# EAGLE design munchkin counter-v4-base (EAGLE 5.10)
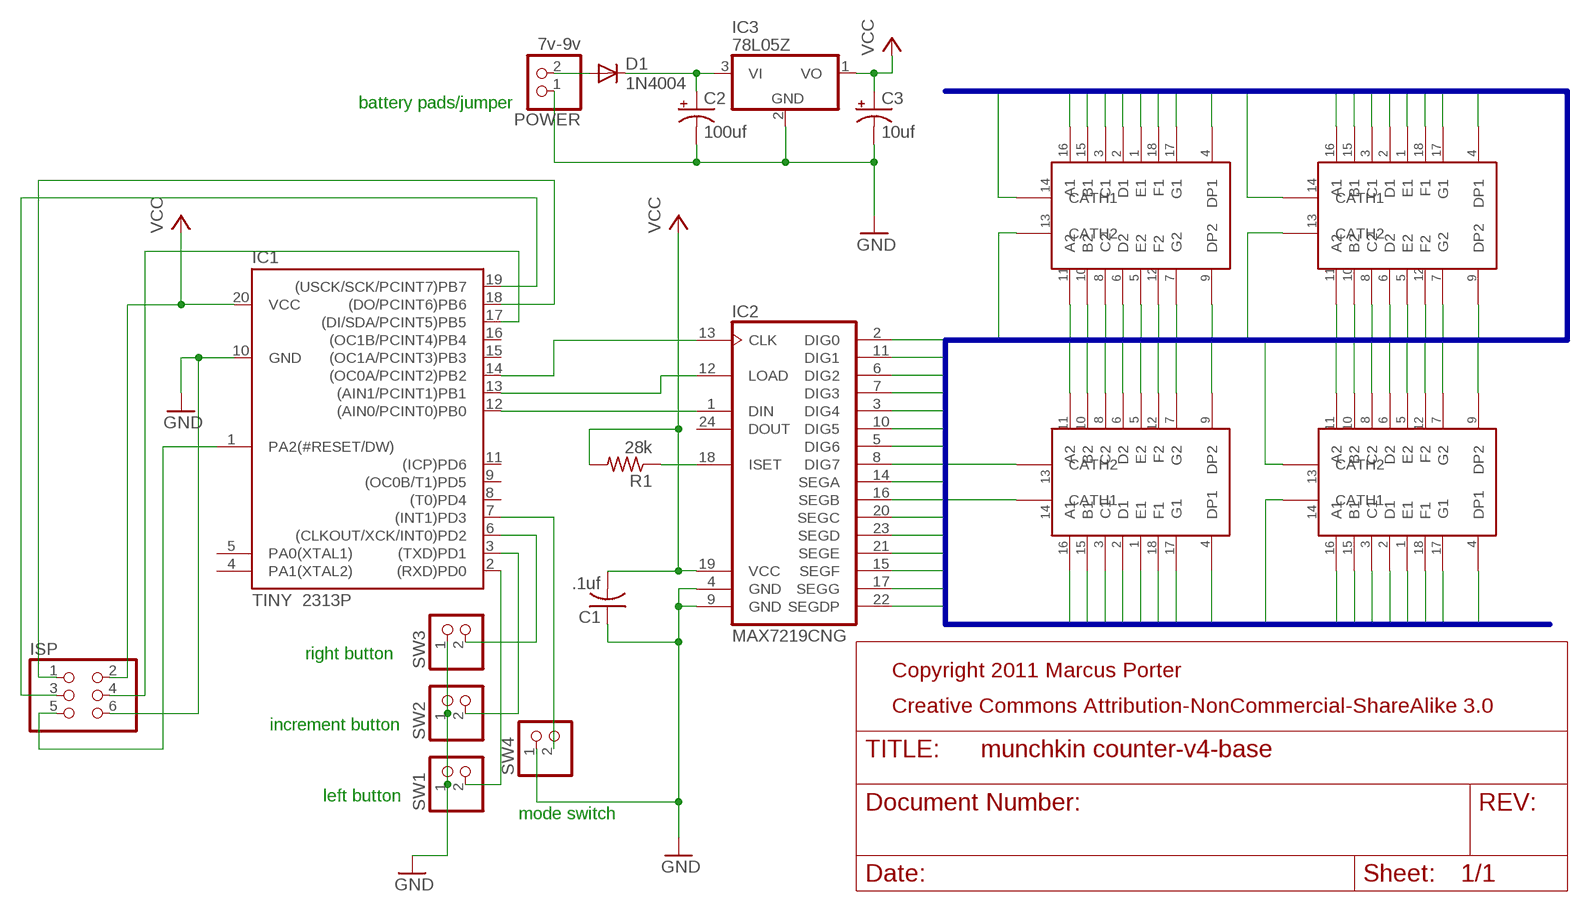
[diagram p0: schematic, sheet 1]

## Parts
C1  .1uf  C-US025-025X050  [C025-025X050]
C2  100uf  CPOL-USE2.5-5  [E2,5-5]
C3  10uf  CPOL-USE2.5-5  [E2,5-5]
D1  1N4004  [DO41-10]
DISPLAY1  DUAL7SEGMENTLEDDUAL7SEGMENT-VIA-CABLE  [2X9HEADER]
DISPLAY2  DUAL7SEGMENTLEDDUAL7SEGMENT-VIA-CABLE  [2X9HEADER]
DISPLAY3  DUAL7SEGMENTLEDDUAL7SEGMENT-VIA-CABLE  [2X9HEADER]
DISPLAY4  DUAL7SEGMENTLEDDUAL7SEGMENT-VIA-CABLE  [2X9HEADER]
IC1  TINY 2313P  TINY2313P  [DIL20]
IC2  MAX7219CNG  [DIL24-3]
IC3  78L05Z  [TO92]
ISP  PINHD-2X3  [2X03]
POWER  7v-9v  PINHD-1X2  [1X02]
R1  28k  R-US_0204/7  [0204/7]
SW1  PINHD-1X2  [1X02]
SW2  PINHD-1X2  [1X02]
SW3  PINHD-1X2  [1X02]
SW4  PINHD-1X2  [1X02]

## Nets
DIG0: DISPLAY1.P14/CATH1(CATH1) IC2.2(DIG0)
DIG1: DISPLAY1.P13/CATH2(CATH2) IC2.11(DIG1)
DIG2: DISPLAY2.P14/CATH1(CATH1) IC2.6(DIG2)
DIG3: DISPLAY2.P13/CATH2(CATH2) IC2.7(DIG3)
DIG4: DISPLAY3.P14/CATH1(CATH1) IC2.3(DIG4)
DIG5: DISPLAY3.P13/CATH2(CATH2) IC2.10(DIG5)
DIG6: DISPLAY4.P14/CATH1(CATH1) IC2.5(DIG6)
DIG7: DISPLAY4.P13/CATH2(CATH2) IC2.8(DIG7)
GND: C1.1 C2.- C3.- IC1.10(GND) IC2.4(GND) IC2.9(GND) IC3.2(GND) ISP.6 POWER.1 SW1.1 SW2.1 SW3.1 SW4.1
N$1: IC1.7((INT1)PD3) SW4.2
N$2: IC1.12((AIN0/PCINT0)PB0) IC2.1(DIN)
N$3: IC1.13((AIN1/PCINT1)PB1) IC2.12(LOAD)
N$4: IC1.14((OC0A/PCINT2)PB2) IC2.13(CLK)
N$5: IC1.2((RXD)PD0) SW1.2
N$6: IC1.3((TXD)PD1) SW2.2
N$7: IC1.6((CLKOUT/XCK/INT0)PD2) SW3.2
N$8: IC2.18(ISET) R1.1
N$9: IC1.18((DO/PCINT6)PB6) ISP.1
N$10: D1.A POWER.2
N$11: IC1.19((USCK/SCK/PCINT7)PB7) ISP.3
N$12: IC1.17((DI/SDA/PCINT5)PB5) ISP.4
N$13: IC1.1(PA2(#RESET/DW)) ISP.5
N$14: C2.+ D1.C IC3.3(VI)
SEGA: DISPLAY1.P11/A2(A2) DISPLAY1.P16/A1(A1) DISPLAY2.P11/A2(A2) DISPLAY2.P16/A1(A1) DISPLAY3.P11/A2(A2) DISPLAY3.P16/A1(A1) DISPLAY4.P11/A2(A2) DISPLAY4.P16/A1(A1) IC2.14(SEGA)
SEGB: DISPLAY1.P10/B2(B2) DISPLAY1.P15/B1(B1) DISPLAY2.P10/B2(B2) DISPLAY2.P15/B1(B1) DISPLAY3.P10/B2(B2) DISPLAY3.P15/B1(B1) DISPLAY4.P10/B2(B2) DISPLAY4.P15/B1(B1) IC2.16(SEGB)
SEGC: DISPLAY1.P3/C1(C1) DISPLAY1.P8/C2(C2) DISPLAY2.P3/C1(C1) DISPLAY2.P8/C2(C2) DISPLAY3.P3/C1(C1) DISPLAY3.P8/C2(C2) DISPLAY4.P3/C1(C1) DISPLAY4.P8/C2(C2) IC2.20(SEGC)
SEGD: DISPLAY1.P2/D2(D1) DISPLAY1.P6/D2(D2) DISPLAY2.P2/D2(D1) DISPLAY2.P6/D2(D2) DISPLAY3.P2/D2(D1) DISPLAY3.P6/D2(D2) DISPLAY4.P2/D2(D1) DISPLAY4.P6/D2(D2) IC2.23(SEGD)
SEGDP: DISPLAY1.P4/DP1(DP1) DISPLAY1.P9/DP2(DP2) DISPLAY2.P4/DP1(DP1) DISPLAY2.P9/DP2(DP2) DISPLAY3.P4/DP1(DP1) DISPLAY3.P9/DP2(DP2) DISPLAY4.P4/DP1(DP1) DISPLAY4.P9/DP2(DP2) IC2.22(SEGDP)
SEGE: DISPLAY1.P1/E1(E1) DISPLAY1.P5/E2(E2) DISPLAY2.P1/E1(E1) DISPLAY2.P5/E2(E2) DISPLAY3.P1/E1(E1) DISPLAY3.P5/E2(E2) DISPLAY4.P1/E1(E1) DISPLAY4.P5/E2(E2) IC2.21(SEGE)
SEGF: DISPLAY1.P12/F2(F2) DISPLAY1.P18/F1(F1) DISPLAY2.P12/F2(F2) DISPLAY2.P18/F1(F1) DISPLAY3.P12/F2(F2) DISPLAY3.P18/F1(F1) DISPLAY4.P12/F2(F2) DISPLAY4.P18/F1(F1) IC2.15(SEGF)
SEGG: DISPLAY1.P7/G2(G2) DISPLAY1.P17/G1(G1) DISPLAY2.P7/G2(G2) DISPLAY2.P17/G1(G1) DISPLAY3.P7/G2(G2) DISPLAY3.P17/G1(G1) DISPLAY4.P7/G2(G2) DISPLAY4.P17/G1(G1) IC2.17(SEGG)
VCC: C1.2 C3.+ IC1.20(VCC) IC2.19(VCC) IC3.1(VO) ISP.2 R1.2
Unconnected: IC1.4(PA1(XTAL2)) IC1.5(PA0(XTAL1)) IC1.8((T0)PD4) IC1.9((OC0B/T1)PD5) IC1.11((ICP)PD6) IC1.15((OC1A/PCINT3)PB3) IC1.16((OC1B/PCINT4)PB4) IC2.24(DOUT)

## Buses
BUS1:DIG[0..7],SEGA,SEGB,SEGC,SEGD,SEGE,SEGF,SEGG,SEGDP

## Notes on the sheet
- battery pads/jumper
- right button
- Copyright 2011 Marcus Porter
- Creative Commons Attribution-NonCommercial-ShareAlike 3.0
- increment button
- left button
- mode switch

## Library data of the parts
C1 = resistor:C-US: CAPACITOR, American symbol
C2 C3 = resistor:CPOL-US: POLARIZED CAPACITOR, American symbol
D1 = diode:1N4004: DIODE
DISPLAY1-DISPLAY4 = mkp:DUAL7SEGMENTLED: Dual 7 segment LED
IC1 = minipov:TINY2313: 8-bit AVR Microcontroller with 2K Bytes Flash Source: http://www.atmel.com .. doc1477.pdf
IC2 = maxim:MAX7219CNG: LED DISPLAY DRIVER
IC3 = linear:78*: Positive VOLTAGE REGULATOR Source: http://cache.national.com/ds/LM/LM78L05.pdf http://www.fairchildsemi.com/ds/LM/LM7805.pdf
ISP = pinhead:PINHD-2X3: PIN HEADER
POWER SW1-SW4 = pinhead:PINHD-1X2: PIN HEADER
R1 = resistor:R-US_: RESISTOR, American symbol

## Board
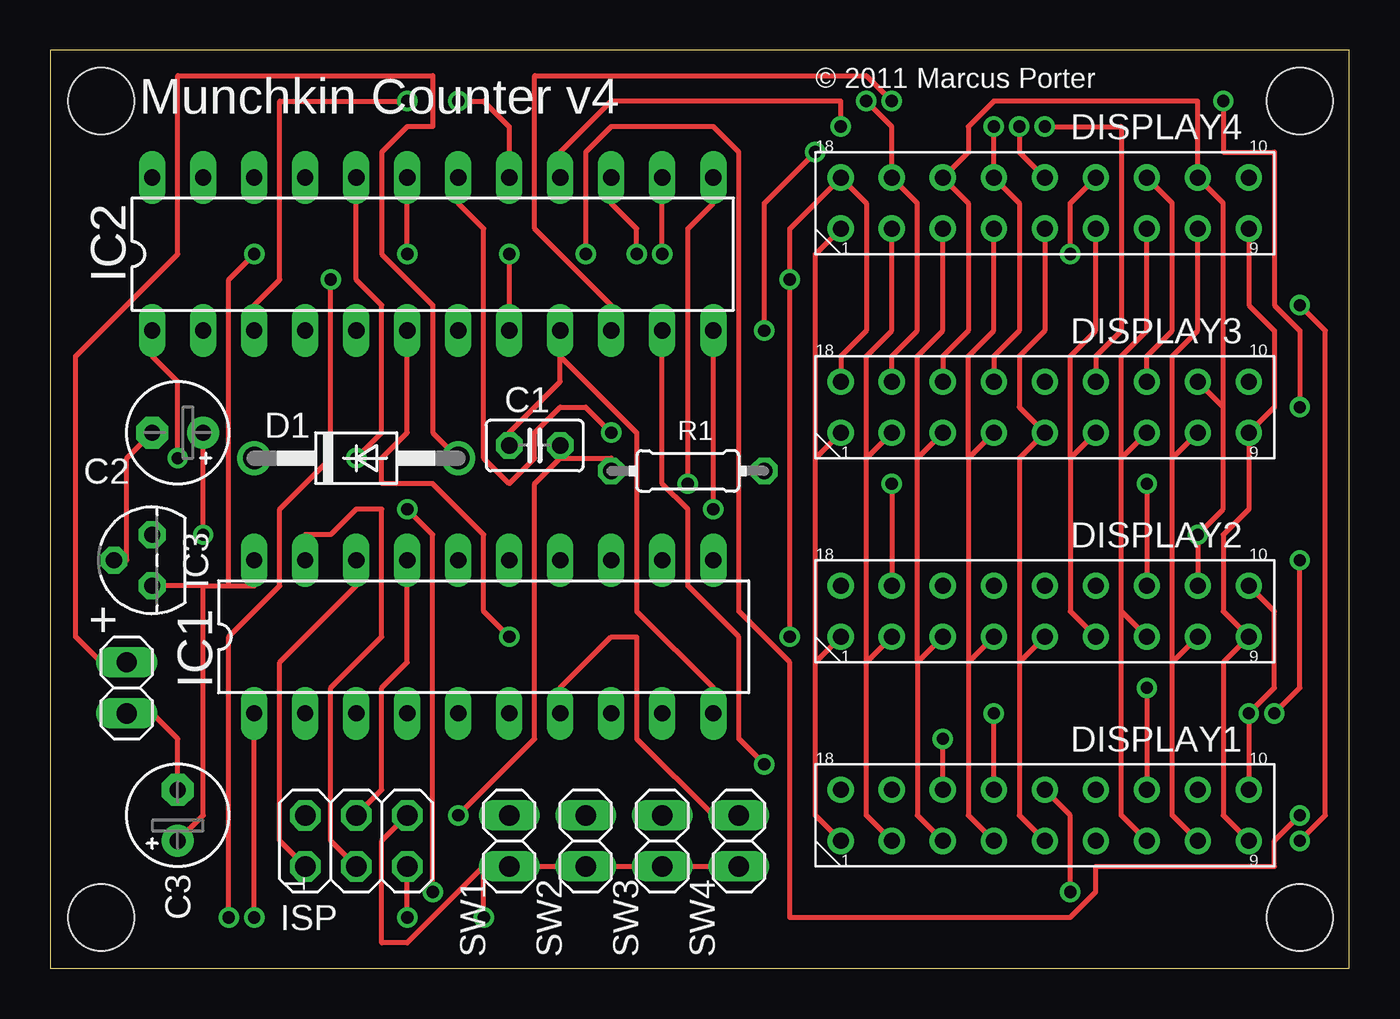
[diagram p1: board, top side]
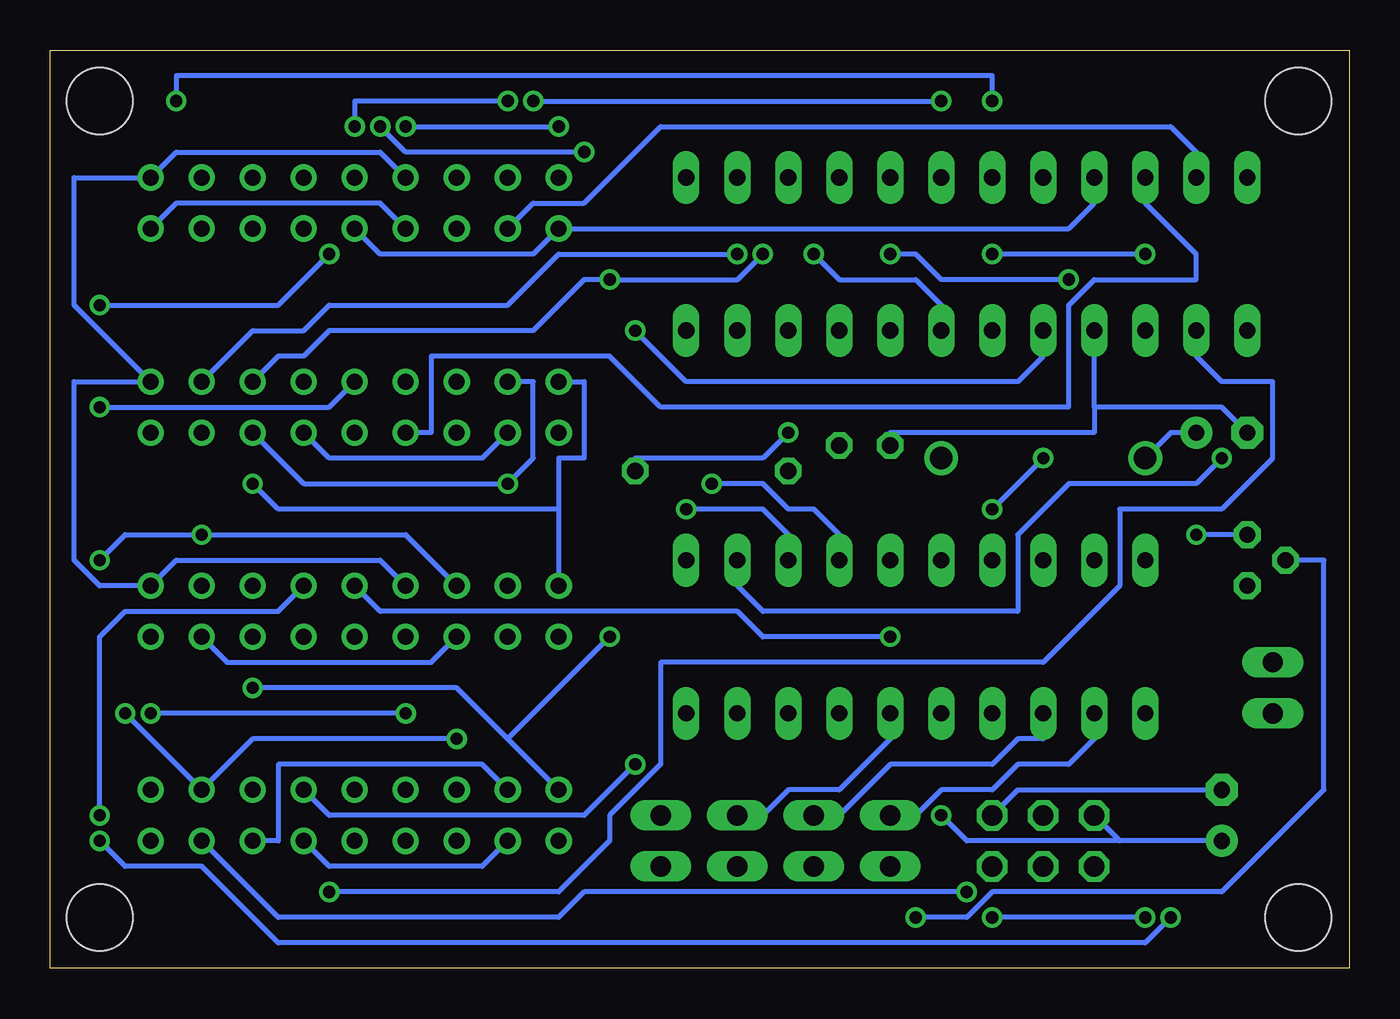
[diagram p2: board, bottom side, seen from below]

Size 64.69 x 45.71 mm. Coordinates in mm from the lower left corner, seen from the top.
Outline: 0,0 64.69,0 64.69,45.71 0,45.71 0,0
Copper layers (1*16): Top 0.035mm / dielectric 1.5mm / Bottom 0.035mm
Design rules "default": minimum track width 10mil, minimum drill 24mil, track to track 8mil, track to pad 8mil, pad to pad 8mil, via to via 8mil, smd to smd 8mil, copper to edge 40mil, drill to drill 8mil, minimum pad ring 10mil, minimum via ring 8mil, stop-mask expansion 4mil, vias tented up to drill 0mil, thermal gap 10mil
Holes 3.3 mm at 2.54,43.18 2.54,2.54 62.23,2.54 62.23,43.18

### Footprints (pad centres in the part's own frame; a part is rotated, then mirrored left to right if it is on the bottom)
C025-025X050 = drill 0.813 octagon: 1 -1.27,0; 2 1.27,0
E2,5-5 = drill 0.813 pad 1.6 round: + -1.27,0 | drill 0.813 pad 1.6 octagon: - 1.27,0
DO41-10 = drill 1.118 round: A 5.08,0; C -5.08,0
2X9HEADER = drill 0.8 round: P1/E1 -10.16,-1.27; P2/D2 -7.62,-1.27; P3/C1 -5.08,-1.27; P4/DP1 -2.54,-1.27; P5/E2 0,-1.27; P6/D2 2.54,-1.27; P7/G2 5.08,-1.27; P8/C2 7.62,-1.27; P9/DP2 10.16,-1.27; P10/B2 10.16,1.27; P11/A2 7.62,1.27; P12/F2 5.08,1.27; P13/CATH2 2.54,1.27; P14/CATH1 0,1.27; P15/B1 -2.54,1.27; P16/A1 -5.08,1.27; P17/G1 -7.62,1.27; P18/F1 -10.16,1.27
DIL20 = drill 0.813 long: 1 -11.43,-3.81; 2 -8.89,-3.81; 3 -6.35,-3.81; 4 -3.81,-3.81; 5 -1.27,-3.81; 6 1.27,-3.81; 7 3.81,-3.81; 8 6.35,-3.81; 9 8.89,-3.81; 10 11.43,-3.81; 11 11.43,3.81; 12 8.89,3.81; 13 6.35,3.81; 14 3.81,3.81; 15 1.27,3.81; 16 -1.27,3.81; 17 -3.81,3.81; 18 -6.35,3.81; 19 -8.89,3.81; 20 -11.43,3.81
DIL24-3 = drill 0.813 long: 1 -13.97,-3.81; 2 -11.43,-3.81; 3 -8.89,-3.81; 4 -6.35,-3.81; 5 -3.81,-3.81; 6 -1.27,-3.81; 7 1.27,-3.81; 8 3.81,-3.81; 9 6.35,-3.81; 10 8.89,-3.81; 11 11.43,-3.81; 12 13.97,-3.81; 13 13.97,3.81; 14 11.43,3.81; 15 8.89,3.81; 16 6.35,3.81; 17 3.81,3.81; 18 1.27,3.81; 19 -1.27,3.81; 20 -3.81,3.81; 21 -6.35,3.81; 22 -8.89,3.81; 23 -11.43,3.81; 24 -13.97,3.81
TO92 = drill 0.813 octagon: 1 -1.27,0; 2 0,1.905; 3 1.27,0
2X03 = drill 1.016 octagon: 1 -2.54,-1.27; 2 -2.54,1.27; 3 0,-1.27; 4 0,1.27; 5 2.54,-1.27; 6 2.54,1.27
1X02 = drill 1.016 long: 1 -1.27,0; 2 1.27,0
0204/7 = drill 0.813 octagon: 1 -3.81,0; 2 3.81,0

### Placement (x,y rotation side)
C1  24.13,26.04 0 top
C2  6.35,26.67 180 top
C3  6.35,7.62 90 top
D1  15.24,25.4 0 top
DISPLAY1  49.53,7.62 0 top
DISPLAY2  49.53,17.78 0 top
DISPLAY3  49.53,27.94 0 top
DISPLAY4  49.53,38.1 0 top
IC1  21.59,16.51 0 top
IC2  19.05,35.56 0 top
IC3  5.08,20.32 90 top
ISP  15.24,6.35 0 top
POWER  3.81,13.97 90 top
R1  31.75,24.77 180 top
SW1  22.86,6.35 90 top
SW2  26.67,6.35 90 top
SW3  30.48,6.35 90 top
SW4  34.29,6.35 90 top

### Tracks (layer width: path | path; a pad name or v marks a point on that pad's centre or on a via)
DIG0  (via drill 0.61)
  Top 0.254: DISPLAY1.P14/CATH1 50.8,7.62 v50.8,3.81
  Bottom 0.254: v50.8,3.81 39.37,3.81 36.83,6.35 36.83,7.62 34.29,10.16 34.29,15.24 15.24,15.24 11.43,19.05 11.43,22.86 6.35,22.86 3.81,25.4 3.81,29.21 6.35,29.21 7.62,30.48 IC2.2
DIG1  (via drill 0.61)
  Top 0.254: v35.56,10.16 34.29,11.43 34.29,16.51 31.75,19.05 31.75,22.86 30.48,24.13 IC2.11
  Bottom 0.254: DISPLAY1.P13/CATH2 50.8,7.62 38.1,7.62 v35.56,10.16
DIG2  (via drill 0.61)
  Top 0.254: v22.86,16.51 21.59,17.78 21.59,21.59 19.05,24.13 16.51,24.13 16.51,25.4 17.78,26.67 IC2.6
  Bottom 0.254: DISPLAY2.P14/CATH1 48.26,17.78 30.48,17.78 29.21,16.51 v22.86,16.51
DIG3  (via drill 0.61)
  Top 0.254: v62.23,7.62 60.96,6.35 60.96,5.08 52.07,5.08 52.07,3.81 50.8,2.54 36.83,2.54 36.83,15.24 34.29,17.78 34.29,40.64 33.02,41.91 27.94,41.91 26.67,40.64 v26.67,35.56
  Bottom 0.254: DISPLAY2.P13/CATH2 53.34,17.78 60.96,17.78 62.23,16.51 v62.23,7.62 | v26.67,35.56 25.4,34.29 21.59,34.29 20.32,33.02 IC2.7
DIG4  (via drill 0.61)
  Top 0.254: v62.23,27.94 62.23,31.75 60.96,33.02 60.96,40.64 58.42,40.64 v58.42,43.18 | v17.78,43.18 11.43,43.18 11.43,34.29 10.16,33.02 IC2.3
  Bottom 0.254: DISPLAY3.P14/CATH1 50.8,27.94 v62.23,27.94 | v58.42,43.18 58.42,44.45 17.78,44.45 v17.78,43.18
DIG5  (via drill 0.61)
  Top 0.254: DISPLAY3.P13/CATH2 52.07,30.48 53.34,31.75 53.34,41.91 v49.53,41.91 | v41.91,43.18 40.64,44.45 24.13,44.45 24.13,36.83 27.94,33.02 IC2.10
  Bottom 0.254: v49.53,41.91 49.53,43.18 v41.91,43.18
DIG6  (via drill 0.61)
  Top 0.254: DISPLAY4.P14/CATH1 48.26,40.64 v48.26,41.91 | v38.1,40.64 35.56,38.1 v35.56,31.75
  Bottom 0.254: v48.26,41.91 46.99,40.64 v38.1,40.64 | v35.56,31.75 33.02,29.21 16.51,29.21 15.24,30.48 IC2.5
DIG7  (via drill 0.61)
  Top 0.254: DISPLAY4.P13/CATH2 50.8,38.1 v50.8,35.56 | v62.23,33.02 63.5,31.75 63.5,7.62 v62.23,6.35 | v8.89,2.54 8.89,16.51 11.43,19.05 11.43,22.86 13.97,25.4 v13.97,34.29 | v22.86,35.56 IC2.8
  Bottom 0.254: v50.8,35.56 53.34,33.02 v62.23,33.02 | v62.23,6.35 60.96,5.08 57.15,5.08 53.34,1.27 10.16,1.27 v8.89,2.54 | v13.97,34.29 20.32,34.29 21.59,35.56 v22.86,35.56
GND  (via drill 0.61)
  Top 0.254: SW4.1 SW3.1 SW2.1 SW1.1 21.59,5.08 | C3.- 6.35,11.43 5.08,12.7 POWER.1 | 21.59,5.08 17.78,1.27 16.51,1.27 16.51,6.35 ISP.6 | C2.- 3.81,25.4 3.81,20.32 IC3.2 | 25.4,30.48 25.4,29.21 22.86,26.67 C1.1 | 25.4,30.48 29.21,26.67 29.21,17.78 33.02,13.97 IC1.10 | 25.4,30.48 IC2.9 | v21.59,2.54 21.59,5.08
  Bottom 0.254: ISP.6 16.51,8.89 C3.- | 12.7,27.94 12.7,26.67 22.86,26.67 C1.1 | 12.7,27.94 IC2.4 | C2.- 6.35,27.94 12.7,27.94 | v21.59,2.54 19.05,2.54 17.78,3.81 6.35,3.81 1.27,8.89 1.27,20.32 IC3.2
N$1
  Top 0.254: IC1.7 25.4,13.97 27.94,16.51 29.21,16.51 29.21,11.43 33.02,7.62 SW4.2
N$2  (via drill 0.61)
  Top 0.254: v6.35,25.4 6.35,29.21 5.08,30.48 IC2.1
  Bottom 0.254: v6.35,25.4 7.62,24.13 13.97,24.13 16.51,21.59 16.51,17.78 29.21,17.78 30.48,19.05 IC1.12
N$3  (via drill 0.61)
  Top 0.254: v33.02,22.86 IC2.12
  Bottom 0.254: v33.02,22.86 29.21,22.86 27.94,21.59 IC1.13
N$4  (via drill 0.61)
  Top 0.254: v31.75,24.13 31.75,36.83 33.02,38.1 IC2.13
  Bottom 0.254: v31.75,24.13 29.21,24.13 27.94,22.86 26.67,22.86 25.4,21.59 IC1.14
N$5
  Bottom 0.254: IC1.2 12.7,11.43 13.97,10.16 16.51,10.16 17.78,8.89 20.32,8.89 21.59,7.62 SW1.2
N$6
  Bottom 0.254: IC1.3 15.24,11.43 16.51,11.43 17.78,10.16 22.86,10.16 25.4,7.62 SW2.2
N$7
  Bottom 0.254: IC1.6 22.86,11.43 25.4,8.89 27.94,8.89 29.21,7.62 SW3.2
N$8  (via drill 0.61)
  Top 0.254: v27.94,26.67 26.67,27.94 25.4,27.94 24.13,26.67 24.13,25.4 22.86,24.13 21.59,25.4 21.59,36.83 20.32,38.1 IC2.18
  Bottom 0.254: v27.94,26.67 29.21,25.4 35.56,25.4 R1.1
N$9
  Top 0.254: ISP.1 11.43,6.35 11.43,15.24 15.24,19.05 IC1.18
N$10
  Top 0.254: POWER.2 2.54,15.24 1.27,16.51 1.27,30.48 6.35,35.56 6.35,44.45 19.05,44.45 19.05,41.91 17.78,41.91 16.51,40.64 16.51,35.56 19.05,33.02 19.05,26.67 D1.A
N$11
  Top 0.254: ISP.3 13.97,6.35 13.97,13.97 16.51,16.51 16.51,22.86 15.24,22.86 13.97,21.59 12.7,21.59 IC1.19
N$12
  Top 0.254: ISP.4 16.51,8.89 16.51,13.97 17.78,15.24 IC1.17
N$13  (via drill 0.61)
  Top 0.254: v17.78,2.54 ISP.5 | v10.16,2.54 IC1.1
  Bottom 0.254: v10.16,2.54 v17.78,2.54
N$14  (via drill 0.61)
  Top 0.254: v7.62,21.59 C2.+
  Bottom 0.254: IC3.3 v7.62,21.59 | C2.+ 8.89,26.67 D1.C
SEGA  (via drill 0.61)
  Top 0.254: DISPLAY1.P16/A1 v44.45,11.43 | DISPLAY3.P16/A1 44.45,30.48 45.72,31.75 45.72,38.1 DISPLAY4.P16/A1 45.72,40.64 45.72,41.91 46.99,43.18 57.15,43.18 DISPLAY4.P11/A2 58.42,38.1 58.42,27.94 | DISPLAY2.P11/A2 v57.15,21.59 58.42,22.86 58.42,27.94 | 58.42,27.94 DISPLAY3.P11/A2 | v30.48,35.56 IC2.14 | v60.96,12.7 62.23,13.97 v62.23,20.32
  Bottom 0.254: v44.45,11.43 54.61,11.43 DISPLAY1.P11/A2 v60.96,12.7 | DISPLAY2.P16/A1 46.99,21.59 v57.15,21.59 60.96,21.59 v62.23,20.32 | v30.48,35.56 39.37,35.56 41.91,33.02 50.8,33.02 52.07,31.75 54.61,31.75 DISPLAY3.P11/A2
SEGB  (via drill 0.61)
  Top 0.254: DISPLAY1.P15/B1 v46.99,12.7 | DISPLAY1.P10/B2 v59.69,12.7 60.96,13.97 60.96,17.78 DISPLAY2.P10/B2 | DISPLAY3.P15/B1 46.99,30.48 48.26,31.75 48.26,38.1 DISPLAY4.P15/B1 v46.99,41.91 | v39.37,41.91 39.37,43.18 27.94,43.18 25.4,40.64 IC2.16
  Bottom 0.254: DISPLAY2.P15/B1 48.26,20.32 58.42,20.32 DISPLAY2.P10/B2 62.23,19.05 63.5,20.32 63.5,29.21 DISPLAY3.P10/B2 63.5,33.02 63.5,39.37 DISPLAY4.P10/B2 58.42,40.64 48.26,40.64 DISPLAY4.P15/B1 | v46.99,12.7 v59.69,12.7 | v46.99,41.91 v39.37,41.91
SEGC  (via drill 0.61)
  Top 0.254: DISPLAY1.P3/C1 43.18,7.62 43.18,15.24 | DISPLAY2.P3/C1 43.18,15.24 | 43.18,25.4 DISPLAY3.P3/C1 | 43.18,15.24 43.18,25.4 | DISPLAY4.P3/C1 44.45,31.75 43.18,30.48 43.18,25.4 | DISPLAY1.P8/C2 55.88,7.62 55.88,15.24 | 55.88,15.24 DISPLAY2.P8/C2 | 55.88,25.4 DISPLAY3.P8/C2 | 55.88,15.24 55.88,25.4 | DISPLAY4.P8/C2 57.15,31.75 55.88,30.48 55.88,25.4 | v15.24,25.4 16.51,26.67 16.51,33.02 15.24,34.29 IC2.20 | v17.78,22.86 19.05,21.59 v19.05,3.81
  Bottom 0.254: v17.78,22.86 v15.24,25.4 | v19.05,3.81 38.1,3.81 39.37,2.54 53.34,2.54 DISPLAY1.P8/C2 | DISPLAY2.P3/C1 45.72,15.24 55.88,15.24 DISPLAY2.P8/C2
SEGD
  Top 0.254: DISPLAY2.P6/D2 50.8,17.78 50.8,25.4 | DISPLAY3.P6/D2 50.8,25.4 | DISPLAY4.P6/D2 52.07,31.75 50.8,30.48 50.8,25.4 | DISPLAY1.P2/D2 40.64,7.62 40.64,15.24 | 40.64,15.24 DISPLAY2.P2/D2 | 40.64,25.4 DISPLAY3.P2/D2 | 40.64,15.24 40.64,25.4 | DISPLAY4.P2/D2 41.91,31.75 40.64,30.48 40.64,25.4
  Bottom 0.254: DISPLAY1.P6/D2 50.8,5.08 43.18,5.08 DISPLAY1.P2/D2 | DISPLAY4.P2/D2 40.64,38.1 38.1,38.1 34.29,41.91 8.89,41.91 7.62,40.64 IC2.23 | DISPLAY3.P6/D2 50.8,25.4 43.18,25.4 DISPLAY3.P2/D2
SEGDP
  Top 0.254: DISPLAY1.P9/DP2 58.42,7.62 58.42,15.24 DISPLAY2.P9/DP2 58.42,17.78 58.42,21.59 59.69,22.86 DISPLAY3.P9/DP2 60.96,27.94 60.96,31.75 59.69,33.02 DISPLAY4.P9/DP2 | DISPLAY1.P4/DP1 45.72,7.62 45.72,15.24 | 45.72,15.24 DISPLAY2.P4/DP1 | DISPLAY3.P4/DP1 45.72,25.4 | 45.72,25.4 45.72,15.24 | DISPLAY4.P4/DP1 46.99,31.75 45.72,30.48 45.72,25.4
  Bottom 0.254: DISPLAY3.P4/DP1 45.72,26.67 45.72,30.48 36.83,30.48 34.29,27.94 13.97,27.94 13.97,33.02 12.7,34.29 7.62,34.29 7.62,35.56 10.16,38.1 IC2.22 | DISPLAY4.P9/DP2 58.42,38.1 48.26,38.1 DISPLAY4.P4/DP1
SEGE
  Top 0.254: DISPLAY1.P5/E2 48.26,7.62 48.26,15.24 | 48.26,15.24 DISPLAY2.P5/E2 | 48.26,15.24 48.26,25.4 DISPLAY3.P5/E2 48.26,27.94 48.26,30.48 49.53,31.75 DISPLAY4.P5/E2 | DISPLAY1.P1/E1 38.1,7.62 38.1,15.24 | 38.1,15.24 DISPLAY2.P1/E1 | 38.1,25.4 DISPLAY3.P1/E1 | 38.1,15.24 38.1,25.4 | DISPLAY4.P1/E1 38.1,35.56 38.1,25.4
  Bottom 0.254: DISPLAY4.P5/E2 48.26,35.56 40.64,35.56 DISPLAY4.P1/E1 13.97,36.83 12.7,38.1 IC2.21
SEGF  (via drill 0.61)
  Top 0.254: DISPLAY3.P12/F2 54.61,30.48 55.88,31.75 55.88,38.1 DISPLAY4.P12/F2 | v29.21,35.56 29.21,36.83 27.94,38.1 IC2.15 | v54.61,13.97 DISPLAY1.P12/F2 | DISPLAY3.P18/F1 39.37,30.48 40.64,31.75 40.64,38.1 DISPLAY4.P18/F1 36.83,36.83 v36.83,34.29 v36.83,16.51 | v54.61,24.13 DISPLAY2.P12/F2
  Bottom 0.254: v29.21,35.56 30.48,34.29 v36.83,34.29 38.1,34.29 40.64,31.75 50.8,31.75 52.07,30.48 53.34,30.48 DISPLAY3.P12/F2 | 41.91,11.43 44.45,13.97 v54.61,13.97 | DISPLAY1.P18/F1 41.91,11.43 | 39.37,22.86 39.37,25.4 38.1,25.4 38.1,29.21 DISPLAY3.P18/F1 | 39.37,22.86 DISPLAY2.P18/F1 | 39.37,22.86 53.34,22.86 v54.61,24.13 | 41.91,11.43 v36.83,16.51
SEGG  (via drill 0.61)
  Top 0.254: v41.91,24.13 DISPLAY2.P17/G1 | DISPLAY3.P17/G1 41.91,30.48 43.18,31.75 43.18,38.1 DISPLAY4.P17/G1 41.91,41.91 v40.64,43.18 | v20.32,43.18 21.59,43.18 22.86,41.91 IC2.17 | 53.34,17.78 DISPLAY2.P7/G2 | 53.34,17.78 53.34,25.4 | 53.34,25.4 DISPLAY3.P7/G2 | DISPLAY4.P7/G2 54.61,31.75 53.34,30.48 53.34,25.4 | DISPLAY1.P7/G2 53.34,7.62 53.34,17.78
  Bottom 0.254: DISPLAY3.P17/G1 40.64,29.21 40.64,25.4 v41.91,24.13 52.07,24.13 DISPLAY3.P7/G2 | v40.64,43.18 v20.32,43.18 | DISPLAY1.P17/G1 43.18,10.16 53.34,10.16 53.34,6.35 DISPLAY1.P7/G2
VCC  (via drill 0.61)
  Top 0.254: 8.89,19.05 10.16,19.05 IC1.20 | 7.62,19.05 8.89,19.05 | 7.62,19.05 IC3.1 | v10.16,35.56 8.89,34.29 8.89,19.05 | v17.78,35.56 IC2.19 | 25.4,25.4 27.94,25.4 R1.2 | 25.4,25.4 24.13,24.13 24.13,11.43 v20.32,7.62 | 25.4,25.4 C1.2 | 7.62,19.05 7.62,7.62 C3.+
  Bottom 0.254: v10.16,35.56 v17.78,35.56 | 11.43,6.35 ISP.2 | C3.+ 11.43,6.35 | v20.32,7.62 19.05,6.35 11.43,6.35

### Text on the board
tNames: © 2011 Marcus Porter | Munchkin Counter v4 | + | 1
